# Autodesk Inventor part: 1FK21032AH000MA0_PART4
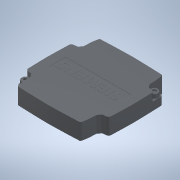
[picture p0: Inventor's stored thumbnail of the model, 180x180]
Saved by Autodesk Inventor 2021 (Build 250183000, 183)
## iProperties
Created: 2025-04
Part Number: 1FK21032AH000MA0_PART4
Material: Generic
Catalog Web Link: www.3dfindit.com
Description: -Servo synchronous motor
Document SubType Name: Modeling
Designer: psAdmin
Mass: 37.514 g
Surface Area: 101.697 cm^2
Volume: 37.514 cm^3
Density: 1 g/cm^3
Appearance: PSOLRGB-38-46-56
Category: PARTsolutions
Title: 1FK21032AH000MA0_PART4
Author: Cadenas PARTsolutions
Comments: Servo synchronous motor
Sending System: PARTsolutions
Preprocessor: ST-DEVELOPER v19.3
PSOL_IDENT_0: {$CADENAS_DATA/23d-libs/siemens_ag/_cat_/45/10/1fk21032ah000ma0.prj},213 {VTYP=3D},{NB=1FK21032AH000
PSOL_IDENT_1: MA0_PART4},{LINA=1FK21032AH000MA0_PART4},{NN=1FK21032AH000MA0_PART4},{NOPRJ=TRUE},{DATE=19.08.2025 1
PSOL_IDENT_2: 4:00:35},{GEOMDATE=30.07.2025 02:02:03},{VERSION=},{LINEID=10},{WBVAR=},{WBNUMERIC=}  {NB=1FK21032AH
PSOL_IDENT_3: 000MA0_PART4},{LINA=1FK21032AH000MA0_PART4},{KT=DUMMY},{PREVIEW=../../../_pool_/14/8e/p_d211_xx_0042
PSOL_IDENT_4: 6j.png},{DESCSHORT=SIMOTICS S-1FK2 HD, SINAMICS S210 3AC 400V-480V, 0.59 Nm, 4500 rpm},{DESCLONG=SIM
PSOL_IDENT_5: OTICS S-1FK2 HD servo motor M0=0.64 Nm; PN = 0.28 kW at nN=4500 rpm (380-480 V); PN = 0.167 kW at nN=
PSOL_IDENT_6: 2500 rpm (200-240 V); degree of protection IP64; cylindrical shaft D14 x 30 mm; absolute encoder 22-
PSOL_IDENT_7: bit + 12-bit multiturn (encoder AM22DQC); with OCC interface; plug size M17, rotatable; SIMOTICS S-1
PSOL_IDENT_8: FK2 servomotorfor a wide range of uses in industrial environments. SIMOTICS S‑1FK2 servomotors are c
PSOL_IDENT_9: ompact synchronous motors with a high dynamic performance that set themselves apart as a result of t
PSOL_IDENT_10: heir high power density, degree of protection and overload capability. The motors are available in t
PSOL_IDENT_11: wo variants: as High Dynamic variant (highest dynamic performance as a result of the low intrinsic m
PSOL_IDENT_12: oment of inertia for applications demanding a high dynamic performance with low moved masses) - and
PSOL_IDENT_13: as Compact variant (precise and stable closed-loop control for medium up to large moved masses as a
PSOL_IDENT_14: result of a medium intrinsic moment of inertia). SIMOTICSS‑1FK2 servomotors fully exploit their stre
PSOL_IDENT_15: ngths in a system with the SINAMICSS210 frequency converter and simple connection using the one cabl
PSOL_IDENT_16: e connection (OCC). Advantages include the short control and positioning times, fast and precise cor
PSOL_IDENT_17: rection of disturbing quantities as well as stable control with a high dynamic performance. The serv
PSOL_IDENT_18: o motors can be configured to address a wide range of requirements. For example with and without hol
PSOL_IDENT_19: ding brake, IP64 or IP65 degree of protection, singleturn or multiturn absolute encoders - to name j
PSOL_IDENT_20: ust a few. Further, the servomotors are available in different shaft heights extending from 20 to 10
PSOL_IDENT_21: 0. A shaft sealing ring is available to achieve an IP65 degree of protection and for subsequent moun
PSOL_IDENT_22: ting at the motor or as spare part. SIMOTICS - the optimum motor for each and every motion control a
PSOL_IDENT_23: pplication.},{INTNO=195125335004},{SUPPLIERALTNO=1FK2103-2AH00-0MA0},{MANUID=1FK21032AH000MA0},{MANU
PSOL_IDENT_24: NAME=Siemens},{MANUTYPEDESC=SYNCHRONOUS MOTOR 1FK2 HD 0,64 NM},{AAU732=SIMOTICS},{AAO057=S-1FK2},{AA
PSOL_IDENT_25: U734=SIMOTICS S-1FK2 HD servo motor M0=0.64 Nm; PN = 0.28 kW at nN=4500 rpm (380-480 V); PN = 0.167
PSOL_IDENT_26: kW at nN=2500 rpm (200-240 V); degree of protection IP64; cylindrical shaft D14 x 30 mm; absolute en
PSOL_IDENT_27: coder 22-bit + 12-bit multiturn (encoder AM22DQC); with OCC interface; plug size M17, rotatable;},{A
PSOL_IDENT_28: AW338=SYNCHRONOUS MOTOR 1FK2 HD 0,64 NM},{AAO742=SIMOTICS},{AAO663=4034106444624},{NOCUPEROU=1},{PRI
PSOL_IDENT_29: CEQUANTITY=1},{QUANTITYMIN=1},{QUANTITYINT=1},{CTN=85015100},{COO=RO},{AAO676=1FK2103-2AH00-0MA0},{A
PSOL_IDENT_30: AO677=Siemens AG},{ORDERUNIT=C62},{CONTENTUNIT=C62}
NB: 1FK21032AH000MA0_PART4
NT: Servo synchronous motor
NBSYN: $MANUID._PART4
LINA: 1FK21032AH000MA0_PART4
CATALOG: SIEMENS
PREVIEW: ../../../_pool_/14/8e/p_d211_xx_00426j.png
DESCSHORT: SIMOTICS S-1FK2 HD, SINAMICS S210 3AC 400V-480V, 0.59 Nm, 4500 rpm
DESCLONG: SIMOTICS S-1FK2 HD servo motor M0=0.64 Nm; PN = 0.28 kW at nN=4500 rpm (380-480 V); PN = 0.167 kW at nN=2500 rpm (200-240 V); degree of protection IP64; cylindr
INTNO: 195125335004
SUPPLIERALTNO: 1FK2103-2AH00-0MA0
MANUID: 1FK21032AH000MA0
MANUNAME: Siemens
MANUTYPEDESC: SYNCHRONOUS MOTOR 1FK2 HD 0,64 NM
AAU732: SIMOTICS
AAO057: S-1FK2
AAU734: SIMOTICS S-1FK2 HD servo motor M0=0.64 Nm; PN = 0.28 kW at nN=4500 rpm (380-480 V); PN = 0.167 kW at nN=2500 rpm (200-240 V); degree of protection IP64; cylindr
AAW338: SYNCHRONOUS MOTOR 1FK2 HD 0,64 NM
AAO742: SIMOTICS
AAO663: 4034106444624.0
NOCUPEROU: 1
PRICEQUANTITY: 1
QUANTITYMIN: 1
QUANTITYINT: 1
CTN: 85015100
COO: RO
ARTICLENO: 1FK21032AH000MA0_PART4
BOMINFO: 1FK21032AH000MA0_PART4
CREATOR: CADENAS GmbH
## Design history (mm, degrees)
feature "2025_04_17_15_00_20_0666"
body "Solid1"
